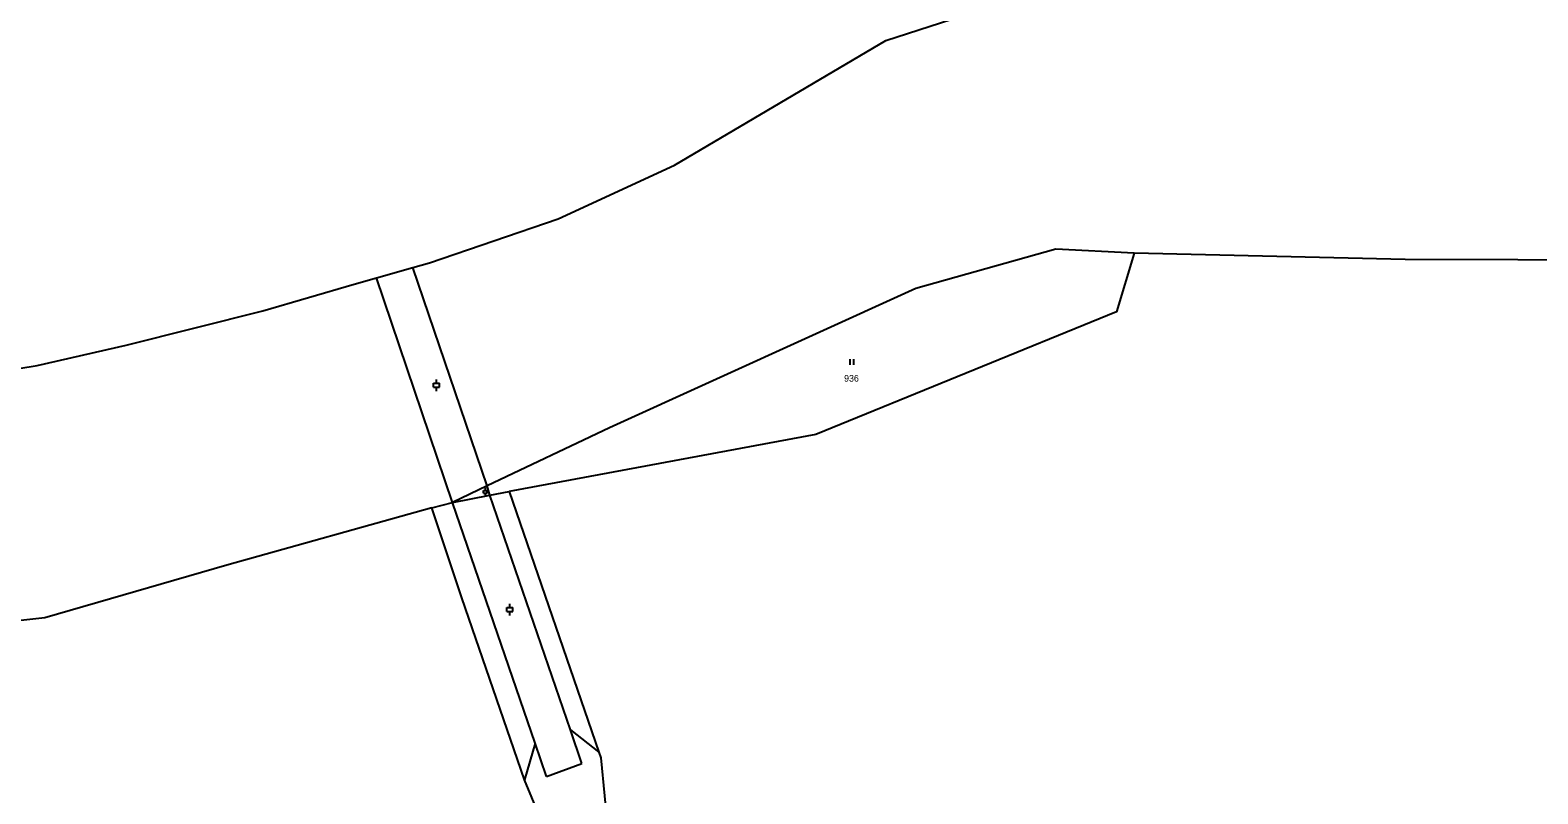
# Model space of a CAD drawing. Extents: x -7483133 to -743907, y -11317770 to -1129777.
# Drawn here: x -750645.6 to -750258.6, y -1130857.7 to -1130661.6 of the extents above; entities that cross this region are included whole.
import ezdxf

# ---------------------------------------------------------------- set-up
doc = ezdxf.new("R2010")
doc.units = 0
for name, color, linetype in [('Hranice parcel', 7, 'Continuous'), ('Parcelní čísla', 7, 'Continuous'), ('Vnitřní kresba', 7, 'Continuous'), ('Značky kultur', 7, 'Continuous')]:
    doc.layers.add(name, color=color, linetype=linetype)

msp = doc.modelspace()

# ---------------------------------------------------------------- linework, layer by layer
at = {"layer": 'Hranice parcel'}
msp.add_line((-750542.51, -1130784.25), (-750537.23, -1130782.88), dxfattribs=at)
for points in [[(-749828.37, -1130639.41), (-749915.33, -1130715.71), (-750029.45, -1130718.38), (-750148.19, -1130720.88), (-750292.64, -1130720.5), (-750362.26, -1130718.85)], [(-750543.14, -1130721.36), (-750510.08, -1130710.04), (-750480.18, -1130696.3), (-750425.99, -1130664.25), (-750395.01, -1130654.25)], [(-750362.26, -1130718.85), (-750382.37, -1130717.85), (-750418.27, -1130727.96), (-750496.94, -1130763.69), (-750528.35, -1130778.65), (-750537.23, -1130782.88)], [(-750562.47, -1130726.85), (-750556.71, -1130725.21), (-750547.39, -1130722.57), (-750543.14, -1130721.36)], [(-750362.26, -1130718.85), (-750366.74, -1130733.92), (-750443.97, -1130765.43), (-750522.68, -1130780.11)], [(-750677.41, -1130753.17), (-750669.01, -1130751.86), (-750643.79, -1130747.71), (-750620.98, -1130742.49), (-750585.9, -1130733.64), (-750562.47, -1130726.85)], [(-750537.23, -1130782.88), (-750527.59, -1130781.02), (-750522.68, -1130780.11)], [(-750522.68, -1130780.11), (-750499.63, -1130847.01), (-750499.12, -1130848.49), (-750497.26, -1130867.97)], [(-750542.51, -1130784.25), (-750595.13, -1130799), (-750641.84, -1130812.5), (-750706.94, -1130819.8)], [(-750511.43, -1130902.47), (-750509.76, -1130887.71), (-750510.81, -1130873.25), (-750518.73, -1130854.13), (-750534.78, -1130807.35), (-750542.51, -1130784.25)]]:
    msp.add_lwpolyline(points, dxfattribs=at)
at = {"layer": 'Vnitřní kresba'}
for p, q in [((-750537.23, -1130782.88), (-750556.71, -1130725.21)), ((-750528.35, -1130778.65), (-750547.39, -1130722.57)), ((-750527.59, -1130781.02), (-750528.35, -1130778.65)), ((-750516.01, -1130844.71), (-750537.23, -1130782.88)), ((-750506.94, -1130841.29), (-750527.59, -1130781.02)), ((-750506.94, -1130841.29), (-750499.63, -1130847.01)), ((-750503.98, -1130849.93), (-750506.94, -1130841.29)), ((-750516.01, -1130844.71), (-750518.73, -1130854.13)), ((-750513.09, -1130853.23), (-750516.01, -1130844.71)), ((-750513.09, -1130853.23), (-750503.98, -1130849.93))]:
    msp.add_line(p, q, dxfattribs=at)
at = {"layer": 'Značky kultur'}
for p, q in [((-750435.15, -1130747.58), (-750435.15, -1130746.08)), ((-750434.15, -1130747.58), (-750434.15, -1130746.08)), ((-750542.05, -1130752.29), (-750540.55, -1130752.29)), ((-750542.05, -1130753.29), (-750542.05, -1130752.29)), ((-750541.3, -1130752.29), (-750541.3, -1130751.29)), ((-750540.55, -1130753.29), (-750540.55, -1130752.29)), ((-750542.05, -1130753.29), (-750540.55, -1130753.29)), ((-750541.3, -1130754.29), (-750541.3, -1130753.29)), ((-750529.27, -1130779.83), (-750528.27, -1130779.83)), ((-750529.27, -1130780.5), (-750529.27, -1130779.83)), ((-750528.77, -1130779.83), (-750528.77, -1130779.16)), ((-750528.27, -1130780.5), (-750528.27, -1130779.83)), ((-750529.27, -1130780.5), (-750528.27, -1130780.5)), ((-750528.77, -1130781.17), (-750528.77, -1130780.5)), ((-750523.26, -1130809.89), (-750521.76, -1130809.89)), ((-750523.26, -1130810.89), (-750523.26, -1130809.89)), ((-750522.51, -1130809.89), (-750522.51, -1130808.89)), ((-750521.76, -1130810.89), (-750521.76, -1130809.89)), ((-750523.26, -1130810.89), (-750521.76, -1130810.89)), ((-750522.51, -1130811.89), (-750522.51, -1130810.89))]:
    msp.add_line(p, q, dxfattribs=at)

# ---------------------------------------------------------------- texts
at = {"layer": 'Parcelní čísla'}
msp.add_text('936', height=1.7, dxfattribs=at).set_placement((-750436.69, -1130751.86))

doc.saveas('drawing.dxf')
